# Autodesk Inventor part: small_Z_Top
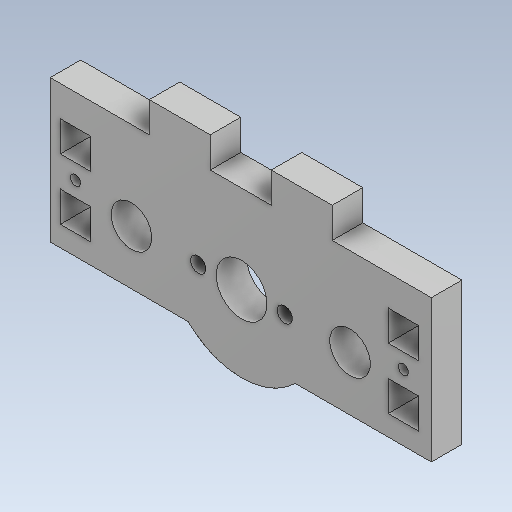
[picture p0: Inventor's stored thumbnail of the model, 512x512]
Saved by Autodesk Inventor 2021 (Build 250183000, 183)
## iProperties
Created: 2026-10
Part Number: small_Z_Top
Material: Steel
Document SubType Name: Modeling
Designer: hp
Density: 7.85 g/cm^3
Appearance: Default
Author: hp
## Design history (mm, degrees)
feature "Body1"
body "Solid1"
